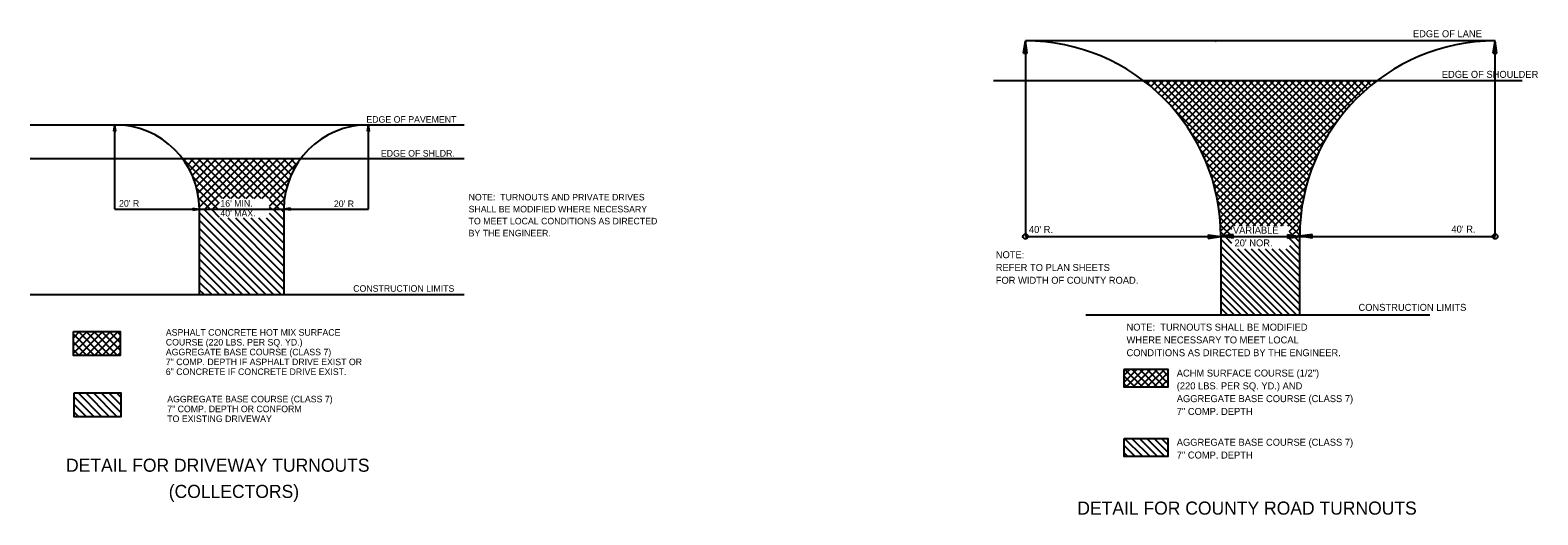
# Model space of a CAD drawing. Extents: x 438659 to 573674, y 10724 to 98600.
# Drawn here: x 441357 to 474526, y 87943 to 98600 of the extents above; entities that cross this region are included whole.
import ezdxf

# ---------------------------------------------------------------- set-up
doc = ezdxf.new("R2010")
doc.units = 0
for name, color, linetype in [('border', 7, 'Continuous'), ('Default', 7, 'Continuous'), ('Dimensions', 7, 'Continuous'), ('T_Vehicle Path Rt', 7, 'Continuous')]:
    doc.layers.add(name, color=color, linetype=linetype)

msp = doc.modelspace()

# ---------------------------------------------------------------- linework, layer by layer
at = {"layer": 'Default'}
for p, q in [((463212, 98091), (463254, 98363)), ((463219, 98091), (463254, 98317)), ((463226, 98091), (463254, 98270)), ((463233, 98091), (463254, 98225)), ((463241, 98091), (463254, 98180)), ((473585, 98363), (463253, 98363)), ((463294, 98091), (463254, 98363)), ((463254, 98363), (463254, 94065)), ((463287, 98091), (463254, 98317)), ((463280, 98091), (463254, 98270)), ((463273, 98091), (463254, 98225)), ((463267, 98091), (463254, 98180)), ((467435, 98354), (467438, 98365)), ((467438, 98361), (467435, 98354)), ((467435, 98354), (467438, 98357)), ((473545, 98091), (473585, 98363)), ((473551, 98091), (473585, 98316)), ((473558, 98091), (473585, 98270)), ((473565, 98091), (473585, 98225)), ((473626, 98091), (473585, 98363)), ((473585, 94065), (473585, 98363)), ((473619, 98091), (473585, 98316)), ((473612, 98091), (473585, 98270)), ((473605, 98091), (473585, 98225)), ((463212, 98091), (463294, 98091)), ((463247, 98091), (463254, 98134)), ((463260, 98091), (463254, 98134)), ((473545, 98091), (473626, 98091)), ((473572, 98091), (473585, 98179)), ((473578, 98091), (473585, 98134)), ((473599, 98091), (473585, 98179)), ((473592, 98091), (473585, 98134)), ((462548, 97495), (474182, 97495)), ((463253, 94065), (467551, 94065)), ((467270, 94103), (467541, 94062)), ((467270, 94103), (467270, 94022)), ((467270, 94097), (467495, 94062)), ((467270, 94090), (467449, 94062)), ((467270, 94082), (467403, 94062)), ((467270, 94075), (467357, 94062)), ((467270, 94069), (467312, 94062)), ((467270, 94022), (467541, 94062)), ((467270, 94049), (467357, 94062)), ((467270, 94035), (467449, 94062)), ((467270, 94028), (467495, 94062)), ((467270, 94042), (467403, 94062)), ((467270, 94056), (467312, 94062)), ((467552, 94065), (467552, 92341)), ((467552, 94065), (469287, 94065)), ((467552, 94065), (468964, 94065)), ((467826, 94109), (467555, 94068)), ((467826, 94028), (467555, 94068)), ((467826, 94103), (467601, 94068)), ((467826, 94035), (467601, 94068)), ((467826, 94096), (467647, 94068)), ((467826, 94042), (467647, 94068)), ((467826, 94089), (467692, 94068)), ((467826, 94048), (467692, 94068)), ((467826, 94082), (467738, 94068)), ((467826, 94055), (467738, 94068)), ((467826, 94075), (467784, 94068)), ((467826, 94062), (467784, 94068)), ((467826, 94028), (467826, 94109)), ((469016, 94105), (469287, 94065)), ((469016, 94105), (469016, 94023)), ((469016, 94098), (469241, 94065)), ((469016, 94091), (469195, 94065)), ((469016, 94084), (469150, 94065)), ((469016, 94077), (469104, 94065)), ((469016, 94071), (469058, 94065)), ((469016, 94023), (469287, 94065)), ((469016, 94051), (469104, 94065)), ((469016, 94037), (469195, 94065)), ((469016, 94030), (469241, 94065)), ((469016, 94044), (469150, 94065)), ((469016, 94058), (469058, 94065)), ((469287, 92341), (469287, 94065)), ((469287, 94065), (473585, 94065)), ((469287, 94065), (469287, 94065)), ((469562, 94109), (469291, 94068)), ((469562, 94028), (469291, 94068)), ((469562, 94103), (469336, 94068)), ((469562, 94035), (469336, 94068)), ((469562, 94096), (469383, 94068)), ((469562, 94042), (469383, 94068)), ((469562, 94089), (469427, 94068)), ((469562, 94048), (469427, 94068)), ((469562, 94082), (469474, 94068)), ((469562, 94055), (469474, 94068)), ((469562, 94075), (469519, 94068)), ((469562, 94062), (469519, 94068)), ((469562, 94028), (469562, 94109)), ((464582, 92341), (472149, 92341)), ((465420, 90856), (465701, 91137)), ((465420, 91008), (465549, 91137)), ((465471, 90755), (465853, 91137)), ((465623, 90755), (466005, 91137)), ((465775, 90755), (466157, 91137)), ((465927, 90755), (466309, 91137)), ((466079, 90755), (466395, 91071)), ((466231, 90755), (466395, 90919)), ((466383, 90755), (466395, 90768))]:
    msp.add_line(p, q, dxfattribs=at)
for points in [[(465420, 91137), (465420, 90755), (466395, 90755), (466395, 91137)], [(465420, 89617), (465420, 89234), (466395, 89234), (466395, 89617)]]:
    msp.add_lwpolyline(points, close=True, dxfattribs=at)
for points in [[(465420, 90997), (465663, 90755)], [(465442, 91137), (465825, 90755)], [(465604, 91137), (465987, 90755)], [(465766, 91137), (466149, 90755)], [(465929, 91137), (466311, 90755)], [(466091, 91137), (466395, 90832)], [(466253, 91137), (466395, 90994)], [(465420, 90834), (465500, 90755)], [(465442, 89617), (465825, 89234)], [(465604, 89617), (465987, 89234)], [(465766, 89617), (466149, 89234)], [(465929, 89617), (466311, 89234)], [(466091, 89617), (466395, 89312)], [(466253, 89617), (466395, 89473)], [(465420, 89476), (465663, 89234)], [(465420, 89314), (465500, 89234)]]:
    msp.add_lwpolyline(points, dxfattribs=at)
for centre in [(463253, 94065), (473585, 94065)]:
    msp.add_circle(centre, 54.2, dxfattribs=at)
for centre, start, end in [((463253, 94065), 0, 90), ((463253, 94065), 0, 90), ((473585, 94065), 90, 180), ((473585, 94065), 90, 180)]:
    msp.add_arc(centre, 4298, start, end, dxfattribs=at)
at = {"layer": 'Dimensions'}
for p, q in [((443198, 96377), (443220, 96521)), ((443198, 96377), (443220, 96521)), ((443241, 96377), (443220, 96521)), ((443241, 96377), (443220, 96521)), ((448777, 96377), (448799, 96521)), ((448777, 96377), (448799, 96521)), ((448820, 96377), (448799, 96521)), ((448820, 96377), (448799, 96521)), ((443198, 96377), (443241, 96377)), ((443198, 96377), (443241, 96377)), ((443202, 96377), (443220, 96497)), ((443202, 96377), (443220, 96497)), ((443205, 96377), (443220, 96472)), ((443205, 96377), (443220, 96472)), ((443209, 96377), (443220, 96448)), ((443209, 96377), (443220, 96448)), ((443213, 96377), (443220, 96424)), ((443213, 96377), (443220, 96424)), ((443216, 96377), (443220, 96400)), ((443216, 96377), (443220, 96400)), ((443238, 96377), (443220, 96497)), ((443238, 96377), (443220, 96497)), ((443234, 96377), (443220, 96472)), ((443234, 96377), (443220, 96472)), ((443231, 96377), (443220, 96448)), ((443231, 96377), (443220, 96448)), ((443227, 96377), (443220, 96424)), ((443227, 96377), (443220, 96424)), ((443223, 96377), (443220, 96400)), ((443223, 96377), (443220, 96400)), ((448777, 96377), (448820, 96377)), ((448777, 96377), (448820, 96377)), ((448781, 96377), (448799, 96497)), ((448781, 96377), (448799, 96497)), ((448784, 96377), (448799, 96472)), ((448784, 96377), (448799, 96472)), ((448788, 96377), (448799, 96448)), ((448788, 96377), (448799, 96448)), ((448792, 96377), (448799, 96424)), ((448792, 96377), (448799, 96424)), ((448795, 96377), (448799, 96400)), ((448795, 96377), (448799, 96400)), ((448817, 96377), (448799, 96497)), ((448817, 96377), (448799, 96497)), ((448813, 96377), (448799, 96472)), ((448813, 96377), (448799, 96472)), ((448809, 96377), (448799, 96448)), ((448809, 96377), (448799, 96448)), ((448806, 96377), (448799, 96424)), ((448806, 96377), (448799, 96424)), ((448802, 96377), (448799, 96400)), ((448802, 96377), (448799, 96400)), ((444935, 94683), (445079, 94661)), ((444935, 94683), (444935, 94640)), ((444935, 94683), (445079, 94661)), ((444935, 94683), (444935, 94640)), ((444935, 94679), (445055, 94661)), ((444935, 94679), (445055, 94661)), ((444935, 94676), (445031, 94661)), ((444935, 94676), (445031, 94661)), ((444935, 94672), (445007, 94661)), ((444935, 94672), (445007, 94661)), ((444935, 94668), (444982, 94661)), ((444935, 94668), (444982, 94661)), ((444935, 94665), (444958, 94661)), ((444935, 94665), (444958, 94661)), ((444935, 94640), (445079, 94661)), ((444935, 94654), (444982, 94661)), ((444935, 94647), (445031, 94661)), ((444935, 94643), (445055, 94661)), ((444935, 94650), (445007, 94661)), ((444935, 94658), (444958, 94661)), ((444935, 94640), (445079, 94661)), ((444935, 94654), (444982, 94661)), ((444935, 94647), (445031, 94661)), ((444935, 94643), (445055, 94661)), ((444935, 94650), (445007, 94661)), ((444935, 94658), (444958, 94661)), ((447083, 94683), (446939, 94661)), ((447083, 94683), (446939, 94661)), ((447083, 94640), (446939, 94661)), ((447083, 94640), (446939, 94661)), ((447083, 94679), (446963, 94661)), ((447083, 94679), (446963, 94661)), ((447083, 94643), (446963, 94661)), ((447083, 94643), (446963, 94661)), ((447083, 94676), (446988, 94661)), ((447083, 94676), (446988, 94661)), ((447083, 94647), (446988, 94661)), ((447083, 94647), (446988, 94661)), ((447083, 94672), (447012, 94661)), ((447083, 94672), (447012, 94661)), ((447083, 94650), (447012, 94661)), ((447083, 94650), (447012, 94661)), ((447083, 94668), (447036, 94661)), ((447083, 94668), (447036, 94661)), ((447083, 94654), (447036, 94661)), ((447083, 94654), (447036, 94661)), ((447083, 94665), (447060, 94661)), ((447083, 94665), (447060, 94661)), ((447083, 94658), (447060, 94661)), ((447083, 94658), (447060, 94661)), ((447083, 94640), (447083, 94683)), ((447083, 94640), (447083, 94683))]:
    msp.add_line(p, q, dxfattribs=at)
at = {"layer": 'T_Vehicle Path Rt'}
for p, q in [((463345, 98363), (463346, 98362)), ((473375, 98363), (473380, 98358)), ((473527, 98363), (473527, 98363)), ((465884, 97495), (466057, 97322)), ((465928, 97429), (465995, 97495)), ((466012, 97361), (466147, 97495)), ((466036, 97495), (469290, 94241)), ((466094, 97291), (466299, 97495)), ((466174, 97218), (466450, 97495)), ((466188, 97495), (469299, 94385)), ((466251, 97144), (466602, 97495)), ((466328, 97068), (466754, 97495)), ((466340, 97495), (469311, 94524)), ((466402, 96991), (466906, 97495)), ((466474, 96911), (467058, 97495)), ((466492, 97495), (469328, 94659)), ((466544, 96829), (467210, 97495)), ((466613, 96746), (467362, 97495)), ((466644, 97495), (469349, 94791)), ((466679, 96660), (467514, 97495)), ((466744, 96573), (467666, 97495)), ((466796, 97495), (469372, 94919)), ((466806, 96483), (467818, 97495)), ((466867, 96392), (467970, 97495)), ((466925, 96298), (468122, 97495)), ((466948, 97495), (469400, 95044)), ((466982, 96203), (468274, 97495)), ((467036, 96105), (468426, 97495)), ((467088, 96005), (468578, 97495)), ((467100, 97495), (469430, 95165)), ((467138, 95903), (468730, 97495)), ((467186, 95799), (468882, 97495)), ((467231, 95693), (469034, 97495)), ((467252, 97495), (469463, 95284)), ((467274, 95583), (469186, 97495)), ((467314, 95472), (469338, 97495)), ((467352, 95358), (469490, 97495)), ((467387, 95241), (469642, 97495)), ((467404, 97495), (469499, 95400)), ((467420, 95121), (469794, 97495)), ((467449, 94998), (469946, 97495)), ((467475, 94872), (470098, 97495)), ((467497, 94743), (470250, 97495)), ((467517, 94610), (470402, 97495)), ((467532, 94473), (470554, 97495)), ((467543, 94333), (470706, 97495)), ((467550, 94187), (470858, 97495)), ((467556, 97495), (469538, 95513)), ((467708, 97495), (469579, 95624)), ((467860, 97495), (469623, 95732)), ((468012, 97495), (469669, 95838)), ((468164, 97495), (469718, 95941)), ((468316, 97495), (469769, 96042)), ((468468, 97495), (469822, 96141)), ((468619, 97495), (469877, 96238)), ((468771, 97495), (469934, 96333)), ((468923, 97495), (469993, 96426)), ((469075, 97495), (470054, 96516)), ((469227, 97495), (470118, 96605)), ((469379, 97495), (470183, 96692)), ((469531, 97495), (470250, 96776)), ((469683, 97495), (470319, 96859)), ((469835, 97495), (470390, 96940)), ((469987, 97495), (470463, 97019)), ((470139, 97495), (470538, 97096)), ((470291, 97495), (470615, 97172)), ((470443, 97495), (470693, 97245)), ((470595, 97495), (470774, 97316)), ((470747, 97495), (470856, 97386)), ((470899, 97495), (470941, 97453)), ((466511, 96869), (469287, 94093)), ((441357, 96521), (450903, 96521)), ((443220, 94661), (443220, 96521)), ((448799, 94661), (448799, 96521)), ((467583, 94069), (470114, 96599)), ((466919, 96308), (468925, 94302)), ((467106, 95969), (468773, 94302)), ((467962, 94295), (469839, 96173)), ((468114, 94295), (469681, 95863)), ((441357, 95777), (450903, 95777)), ((445589, 94896), (444708, 95777)), ((444740, 95729), (444788, 95777)), ((444808, 95627), (444958, 95777)), ((444869, 95518), (445127, 95777)), ((445759, 94896), (444878, 95777)), ((444924, 95404), (445297, 95777)), ((444972, 95282), (445467, 95777)), ((445012, 95153), (445636, 95777)), ((445044, 95015), (445806, 95777)), ((445929, 94896), (445048, 95777)), ((445067, 94868), (445976, 95777)), ((445078, 94709), (446146, 95777)), ((445200, 94661), (446315, 95777)), ((446098, 94896), (445218, 95777)), ((446268, 94896), (445387, 95777)), ((446438, 94896), (445557, 95777)), ((445604, 94896), (446485, 95777)), ((446608, 94896), (445727, 95777)), ((445774, 94896), (446655, 95777)), ((446942, 94732), (445896, 95777)), ((445944, 94896), (446824, 95777)), ((446954, 94889), (446066, 95777)), ((446113, 94896), (446994, 95777)), ((446978, 95035), (446236, 95777)), ((446283, 94896), (447164, 95777)), ((447011, 95171), (446406, 95777)), ((446453, 94896), (447259, 95702)), ((447053, 95300), (446575, 95777)), ((447102, 95420), (446745, 95777)), ((447157, 95534), (446915, 95777)), ((447220, 95642), (447084, 95777)), ((447288, 95743), (447254, 95777)), ((467231, 95692), (468621, 94302)), ((468266, 94295), (469570, 95600)), ((445524, 94792), (444932, 95384)), ((446622, 94896), (447070, 95343)), ((467322, 95449), (468469, 94302)), ((467391, 95229), (468317, 94302)), ((468418, 94295), (469489, 95366)), ((445485, 94661), (445019, 95127)), ((445315, 94661), (445062, 94914)), ((446624, 94728), (446991, 95095)), ((446842, 94661), (446624, 94879)), ((446727, 94661), (446954, 94888)), ((467443, 95025), (468165, 94302)), ((468570, 94295), (469427, 95153)), ((468722, 94295), (469380, 94954)), ((443220, 94661), (445079, 94661)), ((445079, 94661), (445079, 92789)), ((445079, 94661), (446939, 94661)), ((446879, 92789), (445079, 94589)), ((446939, 92899), (445176, 94661)), ((445524, 94484), (445346, 94661)), ((445369, 94661), (445524, 94816)), ((445524, 94653), (445516, 94661)), ((446673, 94661), (446624, 94710)), ((446939, 94256), (446624, 94571)), ((446939, 94426), (446704, 94661)), ((446939, 94596), (446874, 94661)), ((446939, 94661), (446939, 92789)), ((446939, 94661), (448799, 94661)), ((467482, 94834), (468013, 94302)), ((467511, 94653), (467861, 94302)), ((468874, 94295), (469344, 94766)), ((469026, 94295), (469319, 94589)), ((446709, 92789), (445079, 94419)), ((446539, 92789), (445079, 94249)), ((446939, 93068), (445540, 94467)), ((446939, 93238), (445710, 94467)), ((446939, 93408), (445880, 94467)), ((446939, 93577), (446049, 94467)), ((446939, 93747), (446219, 94467)), ((446939, 93917), (446389, 94467)), ((446939, 94087), (446558, 94467)), ((467531, 94481), (467789, 94222)), ((467544, 94316), (467761, 94099)), ((469053, 94171), (469301, 94419)), ((469102, 94068), (469291, 94257)), ((446370, 92789), (445079, 94079)), ((446200, 92789), (445079, 93910)), ((467550, 94158), (467629, 94079)), ((467551, 94005), (469215, 92341)), ((467654, 94054), (467789, 93918)), ((469060, 94168), (469141, 94086)), ((469060, 94016), (469287, 93788)), ((469179, 94048), (469287, 93940)), ((469254, 94068), (469287, 94101)), ((446030, 92789), (445079, 93740)), ((445861, 92789), (445079, 93570)), ((467551, 93853), (469063, 92341)), ((467551, 93700), (468911, 92341)), ((467551, 93548), (468759, 92341)), ((467918, 93790), (469287, 92421)), ((468070, 93790), (469287, 92572)), ((468222, 93790), (469287, 92724)), ((468374, 93790), (469287, 92876)), ((468525, 93790), (469287, 93028)), ((468677, 93790), (469287, 93180)), ((468829, 93790), (469287, 93332)), ((468981, 93790), (469287, 93484)), ((469060, 93864), (469287, 93636)), ((445691, 92789), (445079, 93401)), ((445521, 92789), (445079, 93231)), ((467552, 93396), (468607, 92341)), ((467552, 93244), (468455, 92341)), ((445351, 92789), (445079, 93061)), ((445182, 92789), (445079, 92891)), ((467552, 93092), (468303, 92341)), ((467552, 92940), (468151, 92341)), ((441357, 92789), (450903, 92789)), ((467552, 92788), (467999, 92341)), ((467552, 92636), (467847, 92341)), ((467552, 92484), (467695, 92341)), ((442309, 91835), (442445, 91972)), ((442309, 91666), (442615, 91972)), ((442309, 91496), (442785, 91972)), ((442773, 91448), (442309, 91913)), ((442943, 91448), (442419, 91972)), ((442431, 91448), (442954, 91972)), ((443113, 91448), (442589, 91972)), ((442600, 91448), (443124, 91972)), ((443282, 91448), (442759, 91972)), ((442770, 91448), (443294, 91972)), ((443336, 91564), (442928, 91972)), ((443336, 91734), (443098, 91972)), ((443336, 91904), (443268, 91972)), ((442604, 91448), (442309, 91743)), ((442434, 91448), (442309, 91574)), ((442940, 91448), (443336, 91844)), ((443110, 91448), (443336, 91675)), ((443279, 91448), (443336, 91505)), ((442935, 90100), (442411, 90624)), ((443105, 90100), (442581, 90624)), ((443275, 90100), (442751, 90624)), ((443352, 90192), (442921, 90624)), ((443352, 90362), (443090, 90624)), ((443352, 90532), (443260, 90624)), ((442765, 90100), (442325, 90541)), ((442596, 90100), (442325, 90371)), ((442426, 90100), (442325, 90201))]:
    msp.add_line(p, q, dxfattribs=at)
for points in [[(442309, 91972), (443336, 91972), (443336, 91448), (442309, 91448)], [(442325, 90624), (443352, 90624), (443352, 90100), (442325, 90100)]]:
    msp.add_lwpolyline(points, close=True, dxfattribs=at)
for centre, start, end in [((443220, 94661), 0, 90), ((448799, 94661), 90, 180)]:
    msp.add_arc(centre, 1860, start, end, dxfattribs=at)

# ---------------------------------------------------------------- texts
at = {"layer": 'border'}
for s, p in [('DETAIL FOR DRIVEWAY TURNOUTS ', (442147, 88890)), ('(COLLECTORS)', (444406, 88314)), ('DETAIL FOR COUNTY ROAD TURNOUTS', (464394, 87947))]:
    msp.add_text(s, height=288, dxfattribs=at).set_placement(p)
at = {"layer": 'Default'}
for s, height, p in [('EDGE OF LANE', 153.6, (471777, 98444)), ('EDGE OF SHOULDER', 153.6, (472413, 97552)), ('NOTE:  TURNOUTS AND PRIVATE DRIVES', 144, (451003, 94856)), ('SHALL BE MODIFIED WHERE NECESSARY', 144, (451003, 94593)), ('TO MEET LOCAL CONDITIONS AS DIRECTED', 144, (451003, 94330)), ('BY THE ENGINEER.', 144, (451003, 94066)), ("40' R.", 153.6, (463330, 94141)), ('VARIABLE', 153.6, (467818, 94126)), ("40' R.", 153.6, (472625, 94149)), ("20' NOR.", 153.6, (467853, 93845)), ('NOTE:', 153.6, (462600, 93586)), ('REFER TO PLAN SHEETS', 153.6, (462600, 93305)), ('FOR WIDTH OF COUNTY ROAD.', 153.6, (462600, 93024)), ('CONSTRUCTION LIMITS', 153.6, (470580, 92428)), ('NOTE:  TURNOUTS SHALL BE MODIFIED ', 153.6, (465477, 91993)), ('WHERE NECESSARY TO MEET LOCAL ', 153.6, (465477, 91712)), ('CONDITIONS AS DIRECTED BY THE ENGINEER.', 153.6, (465477, 91431)), ('ACHM SURFACE COURSE (1/2") ', 153.6, (466582, 90983)), ('AGGREGATE BASE COURSE (CLASS 7)', 153.6, (466582, 90421)), ('(220 LBS. PER SQ. YD.) AND ', 153.6, (466582, 90702)), ('7" COMP. DEPTH', 153.6, (466582, 90140)), ('AGGREGATE BASE COURSE (CLASS 7)', 153.6, (466582, 89462)), ('7" COMP. DEPTH', 153.6, (466582, 89181))]:
    msp.add_text(s, height=height, dxfattribs=at).set_placement(p)
at = {"layer": 'T_Vehicle Path Rt'}
for s, p in [('EDGE OF PAVEMENT', (448755, 96566)), ('EDGE OF SHLDR.', (449074, 95820)), ("20' R", (443313, 94720)), ("16' MIN.", (445541, 94719)), ("40' MAX.", (445541, 94503)), ("20' R", (448039, 94711)), ('CONSTRUCTION LIMITS', (448464, 92848)), ('ASPHALT CONCRETE HOT MIX SURFACE', (444342, 91882)), ('AGGREGATE BASE COURSE (CLASS 7) ', (444342, 91450)), ('COURSE (220 LBS. PER SQ. YD.) ', (444342, 91666)), ('7" COMP. DEPTH IF ASPHALT DRIVE EXIST OR', (444342, 91234)), ('6" CONCRETE IF CONCRETE DRIVE EXIST.', (444342, 91018)), ('AGGREGATE BASE COURSE (CLASS 7)', (444373, 90416)), ('7" COMP. DEPTH OR CONFORM', (444373, 90200)), ('TO EXISTING DRIVEWAY', (444373, 89984))]:
    msp.add_text(s, height=144, dxfattribs=at).set_placement(p)

doc.saveas('drawing.dxf')
